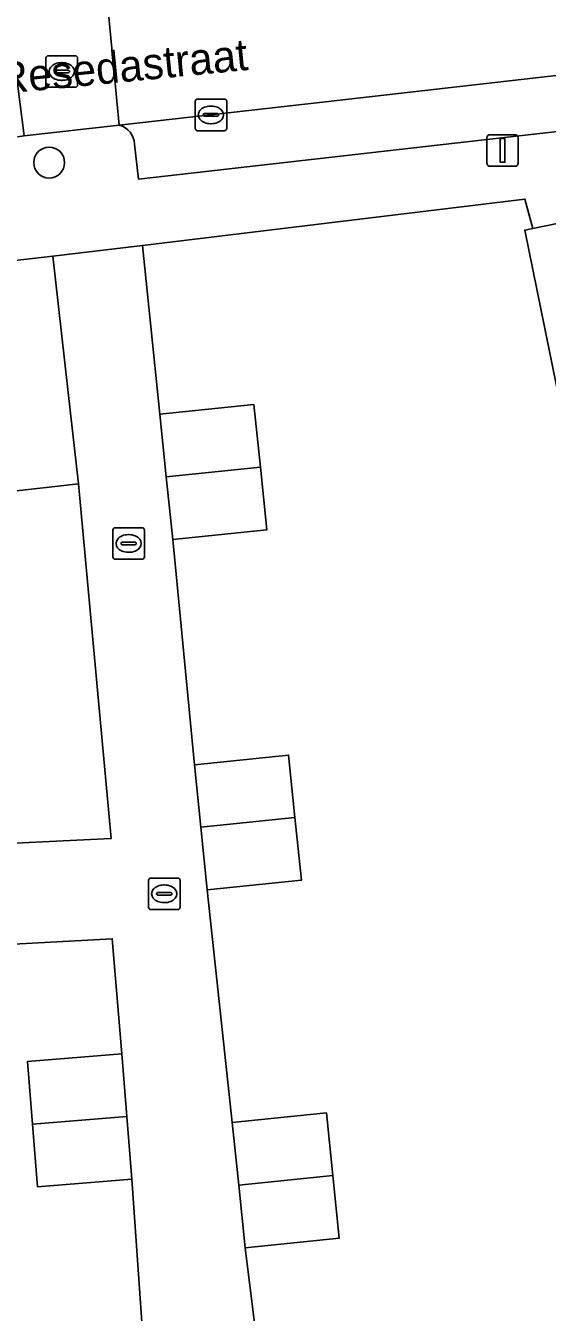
# Model space of a CAD drawing. Extents: x 162250 to 162661, y 380743 to 381606.
# Drawn here: x 162516.38 to 162532.92, y 380860.65 to 380901.41 of the extents above; entities that cross this region are included whole.
import ezdxf

# ---------------------------------------------------------------- set-up
doc = ezdxf.new("R2010")
doc.units = 0
for name, color, linetype in [('IMGEO_Boom', 7, 'Continuous'), ('IMGEO_Erf', 7, 'Continuous'), ('IMGEO_Hek', 7, 'Continuous'), ('IMGEO_Kolk', 7, 'Continuous'), ('IMGEO_Lichtmast', 7, 'Continuous'), ('IMGEO_Muur', 7, 'Continuous'), ('IMGEO_Openbare_ruimte_label', 7, 'Continuous'), ('IMGEO_Pand', 7, 'Continuous'), ('IMGEO_Parkeervlak_open', 7, 'Continuous'), ('IMGEO_Rijbaan_lokaal_open', 7, 'Continuous'), ('IMGEO_Rioolput', 7, 'Continuous'), ('IMGEO_Voetpad_open', 7, 'Continuous')]:
    doc.layers.add(name, color=color, linetype=linetype)

msp = doc.modelspace()

# ---------------------------------------------------------------- linework, layer by layer
at = {"layer": 'IMGEO_Boom'}
msp.add_circle((162517.124, 380897.07), 0.489, dxfattribs=at)
at = {"layer": 'IMGEO_Erf'}
for points in [[(162533.212, 380890.001), (162532.206, 380894.933), (162532.466, 380894.986), (162532.211, 380895.911), (162520.08, 380894.444), (162520.632, 380889.094), (162523.616, 380889.402), (162523.821, 380887.417), (162524.025, 380885.433), (162521.041, 380885.125), (162521.73, 380877.994), (162524.714, 380878.301), (162524.918, 380876.317), (162525.123, 380874.332), (162522.139, 380874.025), (162522.932, 380866.656), (162525.916, 380866.964), (162526.121, 380864.979), (162526.325, 380862.995), (162523.341, 380862.687), (162523.79, 380859.034)], [(162520.255, 380857.616), (162519.748, 380864.861), (162516.758, 380864.617), (162516.596, 380866.604), (162516.434, 380868.591), (162519.424, 380868.835), (162519.127, 380872.478), (162506.03, 380871.77)]]:
    msp.add_lwpolyline(points, dxfattribs=at)
msp.add_lwpolyline([(162518.058, 380886.891), (162512.345, 380886.245), (162506.75, 380885.606), (162501.155, 380884.966), (162500.406, 380884.88), (162500, 380884.834), (162495.438, 380884.313), (162496.559, 380874.478), (162500.151, 380874.654), (162500.005, 380877.65), (162501.998, 380877.747), (162503.992, 380877.845), (162504.138, 380874.849), (162511.4, 380875.277), (162511.253, 380878.273), (162513.247, 380878.371), (162515.24, 380878.468), (162515.387, 380875.472), (162519.087, 380875.653)], close=True, dxfattribs=at)
at = {"layer": 'IMGEO_Hek'}
msp.add_lwpolyline([(162520.08, 380894.444), (162517.236, 380894.1)], dxfattribs=at)
at = {"layer": 'IMGEO_Kolk'}
for p, q in [((162521.753, 380898.154), (162521.753, 380899.006)), ((162521.828, 380899.08), (162522.68, 380899.08)), ((162522.241, 380898.86), (162522.266, 380898.86)), ((162522.754, 380899.006), (162522.754, 380898.154)), ((162522.012, 380898.574), (162522.012, 380898.586)), ((162522.45, 380898.537), (162522.052, 380898.537)), ((162522.055, 380898.623), (162522.453, 380898.623)), ((162522.496, 380898.586), (162522.496, 380898.574)), ((162522.68, 380898.08), (162521.828, 380898.08)), ((162522.264, 380898.3), (162522.239, 380898.3)), ((162519.144, 380884.576), (162519.144, 380885.428)), ((162519.219, 380885.502), (162520.071, 380885.502)), ((162520.145, 380885.428), (162520.145, 380884.576)), ((162519.403, 380884.996), (162519.403, 380885.008)), ((162519.841, 380884.959), (162519.443, 380884.959)), ((162519.446, 380885.045), (162519.844, 380885.045)), ((162519.632, 380885.282), (162519.657, 380885.282)), ((162519.887, 380885.008), (162519.887, 380884.996)), ((162520.071, 380884.502), (162519.219, 380884.502)), ((162519.655, 380884.722), (162519.63, 380884.722)), ((162520.273, 380873.478), (162520.273, 380874.33)), ((162520.348, 380874.404), (162521.2, 380874.404)), ((162521.274, 380874.33), (162521.274, 380873.478)), ((162520.532, 380873.898), (162520.532, 380873.91)), ((162520.575, 380873.947), (162520.973, 380873.947)), ((162520.761, 380874.184), (162520.786, 380874.184)), ((162521.016, 380873.91), (162521.016, 380873.898)), ((162520.97, 380873.861), (162520.572, 380873.861)), ((162520.784, 380873.624), (162520.759, 380873.624)), ((162521.2, 380873.404), (162520.348, 380873.404))]:
    msp.add_line(p, q, dxfattribs=at)
for points in [[(162521.753, 380898.154), (162521.753, 380899.006)], [(162521.828, 380899.08), (162522.68, 380899.08)], [(162522.754, 380899.006), (162522.754, 380898.154)], [(162522.68, 380898.08), (162521.828, 380898.08)], [(162519.144, 380884.576), (162519.144, 380885.428)], [(162519.219, 380885.502), (162520.071, 380885.502)], [(162520.145, 380885.428), (162520.145, 380884.576)], [(162520.071, 380884.502), (162519.219, 380884.502)], [(162520.273, 380873.478), (162520.273, 380874.33)], [(162520.348, 380874.404), (162521.2, 380874.404)], [(162521.274, 380874.33), (162521.274, 380873.478)], [(162521.2, 380873.404), (162520.348, 380873.404)]]:
    msp.add_lwpolyline(points, dxfattribs=at)
for centre, radius, start, end in [((162521.83, 380899.004), 0.0765, 91.552, 178.448), ((162521.83, 380899.004), 0.0765, 91.552, 178.448), ((162522.678, 380899.004), 0.0765, 1.552, 88.448), ((162522.678, 380899.004), 0.0765, 1.552, 88.448), ((162522.052, 380898.583), 0.0403, 85.8775, 175.7526), ((162522.049, 380898.573), 0.0366, 178.938, 274.7102), ((162522.453, 380898.58), 0.043, 264.8664, 352.4533), ((162522.457, 380898.585), 0.0386, 1.7309, 96.639), ((162521.83, 380898.156), 0.0765, 181.552, 268.448), ((162521.83, 380898.156), 0.0765, 181.552, 268.448), ((162522.678, 380898.156), 0.0765, 271.552, 358.448), ((162522.678, 380898.156), 0.0765, 271.552, 358.448), ((162519.221, 380885.426), 0.0765, 91.552, 178.448), ((162519.221, 380885.426), 0.0765, 91.552, 178.448), ((162520.069, 380885.426), 0.0765, 1.552, 88.448), ((162520.069, 380885.426), 0.0765, 1.552, 88.448), ((162519.443, 380885.005), 0.0403, 85.8775, 175.7526), ((162519.44, 380884.995), 0.0366, 178.938, 274.7102), ((162519.844, 380885.002), 0.043, 264.8664, 352.4533), ((162519.848, 380885.007), 0.0386, 1.7309, 96.639), ((162519.221, 380884.578), 0.0765, 181.552, 268.448), ((162519.221, 380884.578), 0.0765, 181.552, 268.448), ((162520.069, 380884.578), 0.0765, 271.552, 358.448), ((162520.069, 380884.578), 0.0765, 271.552, 358.448), ((162520.35, 380874.328), 0.0765, 91.552, 178.448), ((162520.35, 380874.328), 0.0765, 91.552, 178.448), ((162521.198, 380874.328), 0.0765, 1.552, 88.448), ((162521.198, 380874.328), 0.0765, 1.552, 88.448), ((162520.572, 380873.907), 0.0403, 85.8775, 175.7526), ((162520.569, 380873.897), 0.0366, 178.938, 274.7102), ((162520.973, 380873.904), 0.043, 264.8664, 352.4533), ((162520.977, 380873.909), 0.0386, 1.7309, 96.639), ((162520.35, 380873.48), 0.0765, 181.552, 268.448), ((162520.35, 380873.48), 0.0765, 181.552, 268.448), ((162521.198, 380873.48), 0.0765, 271.552, 358.448), ((162521.198, 380873.48), 0.0765, 271.552, 358.448)]:
    msp.add_arc(centre, radius, start, end, dxfattribs=at)
for centre, major_axis, ratio, start_param, end_param in [((162522.24, 380898.58), (-0.387, 0.002), 0.722429, 4.712389, 7.853982), ((162522.265, 380898.58), (-0.39, 0.002), 0.717154, 1.570796, 4.712389), ((162519.631, 380885.002), (-0.387, 0.002), 0.722429, 4.712389, 7.853982), ((162519.656, 380885.002), (-0.39, 0.002), 0.717154, 1.570796, 4.712389), ((162520.76, 380873.904), (-0.387, 0.002), 0.722429, 4.712389, 7.853982), ((162520.785, 380873.904), (-0.39, 0.002), 0.717154, 1.570796, 4.712389)]:
    msp.add_ellipse(centre, major_axis=major_axis, ratio=ratio, start_param=start_param, end_param=end_param, dxfattribs=at)
at = {"layer": 'IMGEO_Lichtmast'}
for p, q in [((162531.108, 380897.953), (162531.898, 380897.953)), ((162531.898, 380897.953), (162531.108, 380897.953)), ((162531.008, 380897.053), (162531.008, 380897.853)), ((162531.008, 380897.853), (162531.008, 380897.053)), ((162531.998, 380897.853), (162531.998, 380897.053)), ((162531.998, 380897.053), (162531.998, 380897.853)), ((162531.898, 380896.953), (162531.108, 380896.953)), ((162531.108, 380896.953), (162531.898, 380896.953))]:
    msp.add_line(p, q, dxfattribs=at)
msp.add_lwpolyline([(162531.428, 380897.828), (162531.578, 380897.828), (162531.578, 380897.078), (162531.428, 380897.078), (162531.428, 380897.828)], dxfattribs=at)
for centre, start, end in [((162531.108, 380897.853), 90, 180), ((162531.108, 380897.853), 90, 180), ((162531.898, 380897.853), 0, 90), ((162531.898, 380897.853), 360, 90), ((162531.108, 380897.053), 180, 270), ((162531.108, 380897.053), 180, 270), ((162531.898, 380897.053), 270, 0), ((162531.898, 380897.053), 270, 0)]:
    msp.add_arc(centre, 0.1, start, end, dxfattribs=at)
at = {"layer": 'IMGEO_Muur'}
msp.add_lwpolyline([(162520.08, 380894.444), (162532.211, 380895.911), (162532.466, 380894.986)], dxfattribs=at)
at = {"layer": 'IMGEO_Pand'}
for points in [[(162533.354, 380889.304), (162540.559, 380890.774), (162539.411, 380896.403), (162532.466, 380894.986), (162532.206, 380894.933), (162533.212, 380890.001)], [(162511.52, 380893.448), (162512.345, 380886.245), (162518.058, 380886.891), (162517.802, 380889.133), (162517.236, 380894.1)], [(162520.632, 380889.094), (162520.837, 380887.11), (162523.821, 380887.417), (162523.616, 380889.402)], [(162523.821, 380887.417), (162520.837, 380887.11), (162521.041, 380885.125), (162524.025, 380885.433)], [(162521.73, 380877.994), (162521.935, 380876.01), (162524.918, 380876.317), (162524.714, 380878.301)], [(162524.918, 380876.317), (162521.935, 380876.01), (162522.139, 380874.025), (162525.123, 380874.332)], [(162519.424, 380868.835), (162516.434, 380868.591), (162516.596, 380866.604), (162519.586, 380866.848)], [(162522.932, 380866.656), (162523.137, 380864.672), (162526.121, 380864.979), (162525.916, 380866.964)], [(162519.586, 380866.848), (162516.596, 380866.604), (162516.758, 380864.617), (162519.748, 380864.861)], [(162526.121, 380864.979), (162523.137, 380864.672), (162523.341, 380862.687), (162526.325, 380862.995)]]:
    msp.add_lwpolyline(points, close=True, dxfattribs=at)
at = {"layer": 'IMGEO_Parkeervlak_open'}
for points in [[(162537.657, 380900.009), (162537.937, 380900.357), (162537.789, 380900.346), (162537.648, 380900.335), (162525.793, 380898.981), (162519.345, 380898.253)], [(162519.833, 380897.654), (162519.955, 380896.549), (162537.79, 380898.573), (162537.657, 380900.009)]]:
    msp.add_lwpolyline(points, dxfattribs=at)
msp.add_arc((162519.191, 380897.629), 0.643, 2.2164, 76.1224, dxfattribs=at)
at = {"layer": 'IMGEO_Rijbaan_lokaal_open'}
for points in [[(162519.345, 380898.253), (162525.793, 380898.981), (162537.648, 380900.335), (162537.789, 380900.346), (162537.353, 380904.639), (162537.072, 380904.685), (162530.592, 380903.867), (162519.094, 380902.597), (162518.93, 380902.579)], [(162516.326, 380897.912), (162519.345, 380898.253), (162518.93, 380902.579), (162515.784, 380902.231)]]:
    msp.add_lwpolyline(points, close=True, dxfattribs=at)
at = {"layer": 'IMGEO_Rioolput'}
for p, q in [((162517.023, 380899.529), (162517.023, 380900.381)), ((162517.098, 380900.455), (162517.95, 380900.455)), ((162518.024, 380900.381), (162518.024, 380899.529)), ((162517.325, 380899.998), (162517.723, 380899.998)), ((162517.511, 380900.235), (162517.536, 380900.235)), ((162517.282, 380899.949), (162517.282, 380899.961)), ((162517.72, 380899.912), (162517.322, 380899.912)), ((162517.534, 380899.675), (162517.509, 380899.675)), ((162517.766, 380899.961), (162517.766, 380899.949)), ((162517.95, 380899.455), (162517.098, 380899.455))]:
    msp.add_line(p, q, dxfattribs=at)
for points in [[(162517.023, 380899.529), (162517.023, 380900.381)], [(162517.098, 380900.455), (162517.95, 380900.455)], [(162518.024, 380900.381), (162518.024, 380899.529)], [(162517.95, 380899.455), (162517.098, 380899.455)]]:
    msp.add_lwpolyline(points, dxfattribs=at)
for centre, radius, start, end in [((162517.1, 380900.379), 0.0765, 91.552, 178.448), ((162517.1, 380900.379), 0.0765, 91.552, 178.448), ((162517.948, 380900.379), 0.0765, 1.552, 88.448), ((162517.948, 380900.379), 0.0765, 1.552, 88.448), ((162517.322, 380899.958), 0.0403, 85.8775, 175.7526), ((162517.727, 380899.96), 0.0386, 1.7309, 96.639), ((162517.319, 380899.948), 0.0366, 178.938, 274.7102), ((162517.723, 380899.955), 0.043, 264.8664, 352.4533), ((162517.1, 380899.531), 0.0765, 181.552, 268.448), ((162517.1, 380899.531), 0.0765, 181.552, 268.448), ((162517.948, 380899.531), 0.0765, 271.552, 358.448), ((162517.948, 380899.531), 0.0765, 271.552, 358.448)]:
    msp.add_arc(centre, radius, start, end, dxfattribs=at)
for centre, major_axis, ratio, start_param, end_param in [((162517.51, 380899.955), (-0.387, 0.002), 0.722429, 4.712389, 7.853982), ((162517.535, 380899.955), (-0.39, 0.002), 0.717154, 1.570796, 4.712389)]:
    msp.add_ellipse(centre, major_axis=major_axis, ratio=ratio, start_param=start_param, end_param=end_param, dxfattribs=at)
at = {"layer": 'IMGEO_Voetpad_open'}
for points in [[(162539.167, 380900.37), (162537.937, 380900.357), (162537.657, 380900.009), (162537.79, 380898.573), (162519.955, 380896.549), (162519.833, 380897.654)], [(162519.345, 380898.253), (162516.326, 380897.912), (162516.124, 380897.889)], [(162491.645, 380891.208), (162491.648, 380891.122), (162493.634, 380891.39), (162494.616, 380891.523), (162500, 380892.136), (162500.33, 380892.174), (162505.925, 380892.811), (162511.52, 380893.448), (162517.236, 380894.1), (162520.08, 380894.444), (162532.211, 380895.911), (162532.466, 380894.986), (162539.411, 380896.403)], [(162523.79, 380859.034), (162523.341, 380862.687), (162523.137, 380864.672), (162522.932, 380866.656), (162522.139, 380874.025), (162521.935, 380876.01), (162521.73, 380877.994), (162521.041, 380885.125), (162520.837, 380887.11), (162520.632, 380889.094), (162520.08, 380894.444), (162517.236, 380894.1), (162517.802, 380889.133), (162518.058, 380886.891), (162519.087, 380875.653), (162515.387, 380875.472)], [(162506.03, 380871.77), (162519.127, 380872.478), (162519.424, 380868.835), (162519.586, 380866.848), (162519.748, 380864.861), (162520.255, 380857.616), (162520.417, 380855.629), (162520.579, 380853.642), (162521.091, 380846.593), (162521.284, 380844.612), (162521.605, 380840.995), (162521.767, 380839.008), (162521.929, 380837.021), (162522.407, 380829.821), (162522.569, 380827.834), (162522.731, 380825.847), (162523.312, 380818.542)]]:
    msp.add_lwpolyline(points, dxfattribs=at)
msp.add_arc((162519.191, 380897.629), 0.643, 2.2164, 76.1224, dxfattribs=at)

# ---------------------------------------------------------------- texts
at = {"layer": 'IMGEO_Openbare_ruimte_label'}
msp.add_text('Resedastraat', height=1, rotation=5.568, dxfattribs=at).set_placement((162515.544, 380899.236))

doc.saveas('drawing.dxf')
